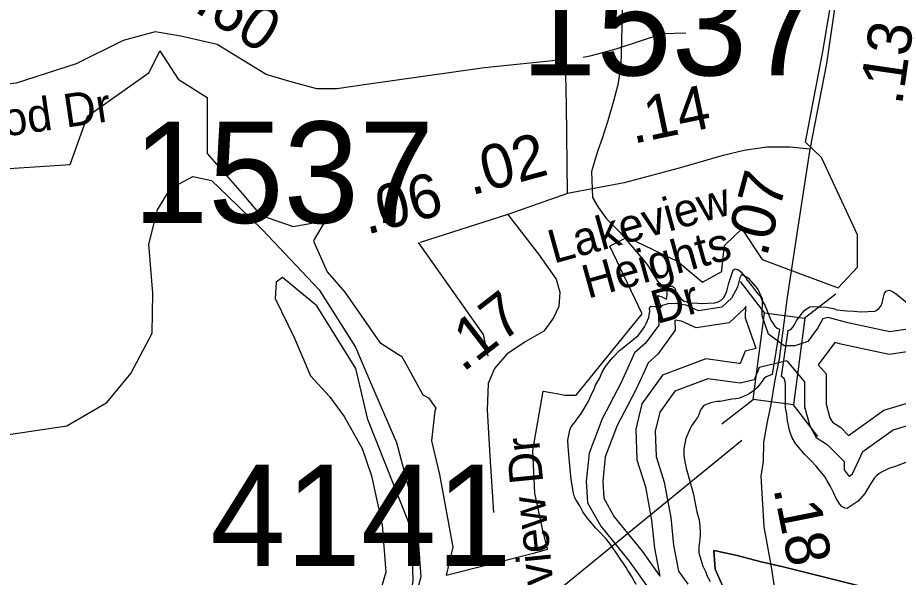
# Model space of a CAD drawing. Extents: x 1662474 to 1856135, y 779280 to 917889.
# Drawn here: x 1715301 to 1717806, y 819482 to 821073 of the extents above; entities that cross this region are included whole.
import ezdxf

# ---------------------------------------------------------------- set-up
doc = ezdxf.new("R2010")
doc.units = 0
for name, color, linetype in [('Cogo Default Point CELL', 7, 'Continuous'), ('Exist Boundary Political City Limit New', 7, 'Continuous'), ('Exist Boundary Political City Limit New Hole', 7, 'Continuous'), ('Exist Hydrographic Creek Single Shore', 7, 'Continuous'), ('Exist Hydrographic Island Shore', 7, 'Continuous'), ('Exist Hydrographic Lake Shore', 7, 'Continuous'), ('Exist Hydrographic Misc Water Feature', 7, 'Continuous'), ('Exist Road Non-System Type 51', 7, 'Continuous'), ('Exist Road Secondary Mileage Tenths English Label', 7, 'Continuous'), ('Exist Road Secondary Structure Standard Bridge CELL', 7, 'Continuous'), ('Exist Road Secondary Structure Standard Bridge Number Label', 7, 'Continuous'), ('Exist Road Secondary Type 51 Attributed', 7, 'Continuous'), ('Exist Road Secondary Type 51 Label', 7, 'Continuous'), ('Map Preparation Boundary City Limit Buffer Line', 7, 'Continuous'), ('Old_Level_44', 7, 'Continuous'), ('Prop DGN Element Guardrail', 7, 'Continuous')]:
    doc.layers.add(name, color=color, linetype=linetype)

msp = doc.modelspace()

# ---------------------------------------------------------------- linework, layer by layer
at = {"layer": 'Exist Boundary Political City Limit New'}
for points in [[(1717694.1, 819458.1), (1717478.1, 819512), (1717415.8, 819526.8), (1717347, 819544.1), (1717290.4, 819556.9), (1717281.5, 819558.9), (1717281.5, 819558.2), (1717284.5, 819505.2), (1717337.2, 819388.2)], [(1717337.2, 819388.2), (1717284.5, 819505.2), (1717281.5, 819558.2), (1717281.5, 819558.9), (1717290.4, 819556.9), (1717347, 819544.1), (1717415.8, 819526.8), (1717478.1, 819512), (1717694.1, 819458.1)]]:
    msp.add_lwpolyline(points, dxfattribs=at)
at = {"layer": 'Exist Boundary Political City Limit New Hole'}
msp.add_lwpolyline([(1715217.1, 820640.2), (1715451.1, 820655.6), (1715499.8, 820792.5), (1715675.2, 820917), (1715706.1, 820978.1), (1715757.4, 820897.8), (1715840.4, 820845.9), (1715840.6, 820686.5), (1715939.6, 820572.7), (1715991.6, 820511.2), (1716084.4, 820479.2), (1716174.5, 820494.8), (1716175.8, 820495), (1716144.9, 820441.8), (1716142.4, 820437.7), (1716162.9, 820393.4), (1716181.4, 820350), (1716231.5, 820293), (1716270.5, 820237), (1716331.6, 820149.4), (1716384.4, 820115.5), (1716393.6, 820109.7), (1716399.2, 820099.5), (1716419.1, 820063.4), (1716453.5, 820001.2), (1716469.8, 819992.5), (1716490.2, 819963.3), (1716489.2, 819960.3), (1716487.4, 819955.5), (1716477.9, 819870.6), (1716500.6, 819774.8), (1716538.8, 819568.2), (1716520.2, 819488.2), (1716772.2, 819551.6), (1716808.1, 819562.5), (1716807, 819567.1), (1716796.1, 819611.9), (1716791.4, 819633.8), (1716772, 819721.6), (1716770.1, 819762.7), (1716766.6, 819842.9), (1716795.4, 820011.2), (1716839.4, 820003.4), (1716856.6, 820000.2), (1716889.5, 820000.2), (1717077.4, 820231.4), (1717076.5, 820233.2), (1716984.9, 820422.9), (1716988.5, 820424.8), (1717034.8, 820448.4), (1717178.9, 820379.9), (1717248.5, 820321.4), (1717303.4, 820351.2), (1717303.9, 820355.8), (1717311.1, 820425), (1717312.6, 820426.5), (1717360.5, 820472.6), (1717418.5, 820385.5), (1717486.5, 820360.2), (1717634.8, 820304.6), (1717689.2, 820363.4), (1717689.2, 820366.6), (1717689.9, 820455.7), (1717587.1, 820675.2), (1717542.2, 820718.9), (1717590.8, 820976.4), (1717619.2, 821145.9)], dxfattribs=at)
at = {"layer": 'Exist Hydrographic Creek Single Shore'}
msp.add_lwpolyline([(1715090.2, 819860.8), (1715441.4, 819912.7), (1715554.8, 819979.1), (1715622.8, 820061.2), (1715684.2, 820176.5), (1715686, 820289.6), (1715674.5, 820429), (1715698.9, 820526.4), (1715736.1, 820587.5), (1715799.1, 820621.6), (1715852.8, 820610.3), (1715899.4, 820564.9), (1715996.8, 820470.9), (1716158.5, 820299.6), (1716262.1, 820136.1), (1716307.5, 820029.2), (1716378.4, 819865.8), (1716435.4, 819651.8), (1716448.2, 819484.1), (1716422.5, 819389.9)], dxfattribs=at)
at = {"layer": 'Exist Hydrographic Island Shore'}
msp.add_lwpolyline([(1716340.9, 819355.3), (1716415.7, 819396.7), (1716426.1, 819474.1), (1716420.9, 819618.7), (1716297, 819931.2), (1716263.5, 820075.8), (1716152.5, 820254), (1716054.4, 820334), (1716036.3, 820321.1), (1716033.8, 820274.6), (1716088, 820163.6), (1716134.4, 820055.1), (1716188.6, 819995.8), (1716229.9, 819938.9), (1716281.5, 819848.6), (1716307.3, 819771.1), (1716338.3, 819631.7), (1716348.6, 819497.4), (1716330.6, 819435.4), (1716322.8, 819401.8), (1716317.7, 819373.4)], close=True, dxfattribs=at)
at = {"layer": 'Exist Hydrographic Lake Shore'}
for points in [[(1716875.8, 819909.6), (1716881.5, 819917.9), (1716887.9, 819925.6), (1716892.9, 819932.9), (1716904.9, 819948.7), (1716924.6, 819983.3), (1716932, 820000.4), (1716941.6, 820020.1), (1716944.8, 820028.4), (1716955.6, 820047.4), (1716964, 820065.2), (1716973.1, 820081.5), (1716981, 820090.7), (1716987, 820099.3), (1716993.4, 820106.7), (1717012.8, 820126.9), (1717020.6, 820132.6), (1717066, 820169.1), (1717078.1, 820185.4), (1717083.6, 820194.3), (1717088.6, 820203.2), (1717096, 820220.8), (1717099.4, 820238.7), (1717098.6, 820246.8), (1717099.4, 820249.7), (1717102.5, 820252.9), (1717124.4, 820251.3), (1717127.5, 820252.3), (1717129.6, 820254.4), (1717129.6, 820257.6), (1717127, 820263.6), (1717123.5, 820273.3), (1717122.2, 820283.1), (1717133.5, 820279.1), (1717146.4, 820272.3), (1717148.2, 820283.6), (1717148, 820295.9), (1717146.9, 820295.6), (1717146.9, 820300.4), (1717148.2, 820303.8), (1717150.6, 820306.7), (1717153.5, 820308.8), (1717156.9, 820309.8), (1717160.2, 820310.1), (1717163.8, 820309.3), (1717165.8, 820308.2), (1717168.6, 820305.9), (1717170, 820303.8), (1717171.2, 820300.4), (1717171.6, 820296.9), (1717170.8, 820294.1), (1717187.6, 820274.4), (1717194.6, 820268.1), (1717204.1, 820264.9), (1717215.4, 820262.3), (1717234.9, 820261.2), (1717245, 820260.2), (1717284.1, 820262.1), (1717293.6, 820265.4), (1717301.8, 820269.4), (1717309.1, 820277.8), (1717313.9, 820285.7), (1717317.2, 820293.8), (1717320.1, 820302.8), (1717323.8, 820317.9), (1717336.4, 820354.7), (1717342.1, 820358.6), (1717351.6, 820356.2), (1717357.9, 820350), (1717370.8, 820335.2), (1717376, 820326.6), (1717388.4, 820311.6), (1717399.1, 820296.2), (1717406.2, 820287.8), (1717413.9, 820279.9), (1717418, 820270.2), (1717426.6, 820254.2), (1717443, 820213.5), (1717454.8, 820195.6), (1717461.1, 820189.9), (1717467.6, 820187.2), (1717446.6, 820058.9), (1717430.1, 820052.3), (1717422.5, 820045), (1717415.4, 820035.8), (1717410.4, 820028.4), (1717404.4, 820021.4), (1717397.9, 820015.6), (1717390.2, 820009.8), (1717382.9, 820005.1), (1717373.9, 820000.1), (1717354.5, 819991.7), (1717344, 819989.1), (1717332.5, 819988.3), (1717298.9, 819982.2), (1717290, 819981.8), (1717272.6, 819977.8), (1717252.4, 819970.2), (1717245.9, 819962.1), (1717241.1, 819953.6)], [(1717831.9, 819810.6), (1717799.9, 819798.2), (1717778.4, 819791.2), (1717759.5, 819782.2), (1717751.4, 819777.8), (1717743.8, 819771.2), (1717737.8, 819764.7), (1717726.1, 819746.1), (1717719.9, 819737.1), (1717710.6, 819720.9), (1717691.8, 819699.3), (1717659.8, 819677.8), (1717653.5, 819679.1), (1717645.4, 819683.6), (1717639.2, 819690.4), (1717628.5, 819706.1), (1717621.1, 819723.2), (1717612.5, 819740.8), (1717602.8, 819758.9), (1717597.2, 819767.3), (1717572.1, 819798.2), (1717558.1, 819813.2), (1717544.8, 819826.6), (1717538.5, 819831.9), (1717513, 819862.3), (1717503.9, 819879.1), (1717496.8, 819896.4), (1717490.2, 819927.4), (1717488.4, 819946.1), (1717485.2, 819963.6), (1717485.2, 820000.1), (1717485.2, 820021.1), (1717485, 820030.3), (1717483.6, 820038.9), (1717480.8, 820047.4), (1717473.1, 820053.4), (1717492.9, 820183.8), (1717500.4, 820187), (1717506.8, 820193.8), (1717516.1, 820211.1), (1717527, 820225.8), (1717531.9, 820233.4), (1717538.8, 820240.2), (1717546.1, 820245.8), (1717553.8, 820250.8), (1717560.8, 820251.8), (1717600.8, 820249.7), (1717610.9, 820248.4), (1717621.1, 820246.3), (1717630.4, 820242.6), (1717659.2, 820239.5), (1717679.1, 820238.4), (1717699.4, 820236.3), (1717738.8, 820238.4), (1717743, 820240.5), (1717750.5, 820245.8), (1717755.5, 820253.1), (1717759.5, 820261.2), (1717762.1, 820270.4), (1717766.2, 820289.6), (1717772.4, 820296.4), (1717781, 820298.2), (1717789.4, 820294.9), (1717799.1, 820287.8), (1717843.2, 820252.1)], [(1717241.1, 819953.6), (1717238.5, 819943.9), (1717234.5, 819936.1), (1717228.8, 819929), (1717217.5, 819912.4), (1717212.5, 819903.2), (1717201.2, 819877), (1717196.2, 819848.9), (1717195.5, 819840), (1717195.5, 819828.4), (1717198.4, 819810.6), (1717200.8, 819801.7), (1717202.5, 819793), (1717214.6, 819748.9), (1717215.4, 819744.2), (1717218.9, 819735.8), (1717223.5, 819717.9), (1717228.8, 819687.5), (1717233, 819668.1), (1717238.5, 819648.4), (1717240.1, 819639.2), (1717242.1, 819611.4), (1717241.9, 819600.9), (1717240.4, 819582), (1717238.5, 819571), (1717238, 819561.6), (1717238, 819552.4), (1717250, 819514.3), (1717257.9, 819497.5), (1717261.6, 819487.8), (1717271, 819470.2)], [(1717060.2, 819461.8), (1717047.1, 819485.7), (1717036.1, 819502.2), (1717031.6, 819510.4), (1716988.6, 819574.7), (1716975.2, 819592), (1716952.1, 819615.9), (1716945.4, 819622.4), (1716920.9, 819651.8), (1716908.9, 819668.9), (1716899.9, 819685.9), (1716889.4, 819701.2), (1716885, 819710.6), (1716882.1, 819721.4), (1716875.2, 819760.2), (1716872.9, 819789.6), (1716869.5, 819821.4), (1716868.1, 819842.6), (1716866.6, 819853.7), (1716866.1, 819871.8), (1716867.4, 819881.8), (1716871.6, 819900.6), (1716875.8, 819909.6)]]:
    msp.add_lwpolyline(points, dxfattribs=at)
at = {"layer": 'Exist Hydrographic Misc Water Feature'}
msp.add_lwpolyline([(1717020.9, 821119.8), (1717016.3, 820937.8), (1717007.9, 820881.3), (1716995.7, 820835.6), (1716979.4, 820779.4), (1716963.2, 820729.6), (1716951.1, 820695.4), (1716932.9, 820635.8), (1716936.5, 820561.9), (1716952.3, 820533.7), (1716976.2, 820501.2), (1717014.2, 820463.5), (1717091.7, 820370.8), (1717126, 820316)], dxfattribs=at)
at = {"layer": 'Exist Road Non-System Type 51'}
for points in [[(1716909.5, 820959.9), (1716933.2, 820965.4), (1717003.6, 820984.1), (1717136.1, 821027.9), (1717201.5, 821029.8)], [(1716639.2, 820110.6), (1716626.4, 820172), (1716441.4, 820433.9)]]:
    msp.add_lwpolyline(points, dxfattribs=at)
at = {"layer": 'Exist Road Secondary Structure Standard Bridge CELL'}
for p, q in [((1717425.8, 820233.4), (1717356.8, 820323.1)), ((1717538, 820218.7), (1717627.8, 820287.7)), ((1717303.4, 819918.7), (1717393.2, 819987.7)), ((1717577, 819883), (1717508, 819972.7))]:
    msp.add_line(p, q, dxfattribs=at)
msp.add_lwpolyline([(1717393.2, 819987.7), (1717425.3, 820233.5), (1717540.1, 820218.5), (1717508, 819972.7)], close=True, dxfattribs=at)
at = {"layer": 'Exist Road Secondary Structure Standard Bridge Number Label'}
msp.add_line((1717360.4, 819870.9), (1715707.3, 818524.3), dxfattribs=at)
at = {"layer": 'Exist Road Secondary Type 51 Attributed'}
msp.add_line((1716865, 820573), (1716695.7, 820513), dxfattribs=at)
for points in [[(1717163.3, 822624.6), (1717297.4, 822355.7), (1717437.3, 822121.5), (1717530.1, 821945.4), (1717610.5, 821725.9), (1717629.1, 821648.7), (1717641.4, 821563.4), (1717650.7, 821452.1), (1717647.6, 821325.4), (1717638.3, 821198.7), (1717622.9, 821090.5), (1717601.2, 820942.2), (1717553.7, 820699.2)], [(1716865, 820573), (1716862.1, 820824.8), (1716859.1, 820953.5), (1716629.3, 820929.6), (1716293.6, 820882.6), (1716208.6, 820870.5), (1716151.9, 820870.5), (1716075.1, 820890.7), (1716008.4, 820910.8), (1715868.7, 820995.8), (1715765.4, 821020.1), (1715692.5, 821032.2), (1715601.4, 821007.9), (1715467.7, 820941.1), (1715297.6, 820886.5), (1715036.3, 820856.1), (1714659.6, 820807.6), (1714143.2, 820759)], [(1717553.7, 820699.2), (1717498, 820704.2), (1717432.1, 820704.2), (1717367.6, 820695.4), (1717303.7, 820679.9), (1717182.2, 820645.3), (1717026, 820603.6), (1716865, 820573)], [(1717553.7, 820699.2), (1717522.3, 820489.1), (1717489.5, 820278.1), (1717466.6, 820103.1)], [(1716695.7, 820513), (1716446.4, 820433.7)], [(1716695.7, 820513), (1716782.7, 820400.4), (1716833, 820330), (1716843, 820292.3), (1716840.5, 820252.1), (1716825.4, 820219.5), (1716797.8, 820181.8), (1716745, 820151.6), (1716692.2, 820116.4), (1716657, 820076.2), (1716639.4, 820033.5), (1716636.8, 819958.2), (1716644.4, 819827.5), (1716654.4, 819666.7)], [(1717466.6, 820103.1), (1717453.7, 820038.2), (1717443.5, 819973.8), (1717433, 819924.1), (1717422.5, 819866.6), (1717421.2, 819811.5), (1717414.3, 819770.2), (1717423.6, 819626.2), (1717444.2, 819512.6), (1717455.4, 819437.4), (1717468.9, 819340.6), (1717462.2, 819241.5), (1717446.4, 819155.9), (1717396.8, 819009.5), (1717349.5, 818887.9), (1717326.9, 818829.3), (1717293.1, 818738), (1717267.8, 818674.7), (1717248.8, 818620.9), (1717144.3, 818358.3), (1717071.5, 818156.6)]]:
    msp.add_lwpolyline(points, dxfattribs=at)
at = {"layer": 'Map Preparation Boundary City Limit Buffer Line'}
for points in [[(1715217.1, 820640.2), (1715451.1, 820655.6), (1715499.8, 820792.5), (1715675.2, 820917), (1715706.1, 820978.1), (1715757.4, 820897.8), (1715840.4, 820845.9), (1715840.6, 820686.5), (1715939.6, 820572.7), (1715991.6, 820511.2), (1716084.4, 820479.2), (1716174.5, 820494.8), (1716175.8, 820495), (1716144.9, 820441.8), (1716142.4, 820437.7), (1716162.9, 820393.4), (1716181.4, 820350), (1716231.5, 820293), (1716270.5, 820237), (1716331.6, 820149.4), (1716384.4, 820115.5), (1716393.6, 820109.7), (1716399.2, 820099.5), (1716419.1, 820063.4), (1716453.5, 820001.2), (1716469.8, 819992.5), (1716490.2, 819963.3), (1716489.2, 819960.3), (1716487.4, 819955.5), (1716477.9, 819870.6), (1716500.6, 819774.8), (1716538.8, 819568.2), (1716520.2, 819488.2), (1716772.2, 819551.6), (1716808.1, 819562.5), (1716807, 819567.1), (1716796.1, 819611.9), (1716791.4, 819633.8), (1716772, 819721.6), (1716770.1, 819762.7), (1716766.6, 819842.9), (1716795.4, 820011.2), (1716839.4, 820003.4), (1716856.6, 820000.2), (1716889.5, 820000.2), (1717077.4, 820231.4), (1717076.5, 820233.2), (1716984.9, 820422.9), (1716988.5, 820424.8), (1717034.8, 820448.4), (1717178.9, 820379.9), (1717248.5, 820321.4), (1717303.4, 820351.2), (1717303.9, 820355.8), (1717311.1, 820425), (1717312.6, 820426.5), (1717360.5, 820472.6), (1717418.5, 820385.5), (1717486.5, 820360.2), (1717634.8, 820304.6), (1717689.2, 820363.4), (1717689.2, 820366.6), (1717689.9, 820455.7), (1717587.1, 820675.2), (1717542.2, 820718.9), (1717590.8, 820976.4), (1717619.2, 821145.9)], [(1717694.1, 819458.1), (1717478.1, 819512), (1717415.8, 819526.8), (1717347, 819544.1), (1717290.4, 819556.9), (1717281.5, 819558.9), (1717281.5, 819558.2), (1717284.5, 819505.2), (1717337.2, 819388.2)], [(1717337.2, 819388.2), (1717284.5, 819505.2), (1717281.5, 819558.2), (1717281.5, 819558.9), (1717290.4, 819556.9), (1717347, 819544.1), (1717415.8, 819526.8), (1717478.1, 819512), (1717694.1, 819458.1)]]:
    msp.add_lwpolyline(points, dxfattribs=at)
at = {"layer": 'Old_Level_44'}
for points in [[(1717481.3, 820140.2), (1717436.6, 820173.3), (1717418.2, 820225.8), (1717419.2, 820272.7), (1717405.9, 820302.5), (1717381.7, 820330.8), (1717360.8, 820342.6), (1717359.8, 820342.5), (1717354.7, 820333), (1717348.4, 820306.7), (1717331.7, 820276), (1717303.7, 820249.6), (1717237.6, 820239.6), (1717202.8, 820255.2), (1717170.9, 820260.4), (1717150, 820259.6), (1717132.3, 820253.5), (1717123.2, 820241.7), (1717124.2, 820199.3), (1717087.1, 820147.5), (1717055.9, 820120.2), (1717040.7, 820086.2), (1717016.2, 820034.1), (1716963.8, 819932.8), (1716926.1, 819835.5), (1716918.4, 819756), (1716922, 819693.9), (1716959.3, 819627.8), (1717039.9, 819528.5), (1717094.3, 819452.3)], [(1718032.8, 820308.2), (1718078.5, 820210.3), (1717900.1, 820133.8), (1717779.3, 820115.6), (1717647.4, 820143.6), (1717625.2, 820149.5), (1717578, 820086.5)], [(1717401.4, 820132.8), (1717371.3, 820218.3), (1717372.1, 820252.6), (1717369.1, 820247.2), (1717325, 820205.7), (1717231.1, 820191.4), (1717189.3, 820210.1), (1717170.6, 820213.2), (1717171.3, 820184.8), (1717121.9, 820116), (1717094.3, 820091.9), (1717083.1, 820066.7), (1717058.1, 820013.4), (1717006.4, 819913.6), (1716971.9, 819824.6), (1716965.1, 819755.1), (1716967.9, 819707.4), (1716998, 819654.1), (1717077, 819556.7), (1717127.6, 819485.9)], [(1717882.6, 820195.5), (1717781.2, 820180.3), (1717662.2, 820205.5), (1717606.2, 820220.3), (1717590.6, 820216.4), (1717576.8, 820191), (1717548, 820152.6), (1717511, 820140.2), (1717481.3, 820140.2)], [(1717401.4, 820132.8), (1717369.9, 820125), (1717355.6, 820090.3), (1717353.3, 820089.7), (1717257.9, 820103.1), (1717135.4, 820056.7), (1717076.3, 819975.4), (1717059.1, 819903.1), (1717062, 819816.6), (1717086.8, 819739.8), (1717103.9, 819644.8), (1717112.3, 819565.2), (1717127.6, 819485.9)], [(1717488.2, 820097.4), (1717410.1, 820078.3), (1717395.6, 820043.2), (1717355.8, 820033.9), (1717264.2, 820046.7), (1717170.2, 820011.1), (1717127.3, 819952), (1717114.3, 819897.6), (1717116.7, 819826.1), (1717140.3, 819753.1), (1717158.4, 819652.6), (1717166.7, 819573.4), (1717180.8, 819500.4), (1717207.4, 819463.2)], [(1717488.2, 820097.4), (1717539.3, 820037.8), (1717539.3, 819966.4), (1717554.4, 819912.6), (1717572.5, 819880), (1717603.3, 819860.2), (1717652.1, 819811.3), (1717652.1, 819787.4), (1717666, 819768.9), (1717675.7, 819776.8), (1717704.5, 819839.6), (1717791.2, 819901.6), (1717891, 819931)], [(1717578, 820086.5), (1717600.4, 820060.3), (1717600.4, 819974.8), (1717611.2, 819936), (1717618.4, 819923.1), (1717641.8, 819908), (1717664.1, 819885.7), (1717764.1, 819957.2), (1717882.2, 819992)]]:
    msp.add_lwpolyline(points, dxfattribs=at)

# ---------------------------------------------------------------- texts
at = {"layer": 'Cogo Default Point CELL'}
for s, p in [('1537', (1716732.9, 820908.4)), ('1537', (1715629.2, 820489.3)), ('4141', (1715849.1, 819514.7))]:
    msp.add_text(s, height=288, dxfattribs=at).set_placement(p)
at = {"layer": 'Exist Road Secondary Mileage Tenths English Label'}
for s, rotation, p in [('.60', 327.5542, (1715799.3, 821092.8)), ('.14', 11.8588, (1717051.5, 820713.6)), ('.02', 15.1189, (1716591.2, 820567.1)), ('.06', 15.0699, (1716294, 820455.4)), ('.07', 74.8939, (1717431, 820389.7)), ('.17', 37.7322, (1716567.3, 820062.8)), ('.18', 281.281, (1717450, 819734.9))]:
    msp.add_text(s, height=125, rotation=rotation, dxfattribs=at).set_placement(p)
at = {"layer": 'Exist Road Secondary Type 51 Label'}
for s, rotation, p in [('Pennywood Dr', 8.3927, (1714747.3, 820657.8)), ('Lakeview', 15.5325, (1716825.5, 820373.3)), (' Heights', 15.5325, (1716888.5, 820264.2)), (' Dr', 15.5325, (1717084.5, 820192.1)), ('Springview Dr', 95.6268, (1716860.7, 819098.6))]:
    msp.add_text(s, height=95, rotation=rotation, dxfattribs=at).set_placement(p)
at = {"layer": 'Prop DGN Element Guardrail'}
msp.add_text('.13', height=125, rotation=81.6984, dxfattribs=at).set_placement((1717815.9, 820821.2))

doc.saveas('drawing.dxf')
